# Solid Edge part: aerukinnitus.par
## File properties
Author: Argo
Template: Normal.par
Last saved by: Argo
Revision: 9
Application: Solid Edge
Material: ABS Plastic, medium impact
Face Style: Black
Fill Style: ANSI34(Plastic)
Virtual Style: Black (Shiny)
Coef. of Thermal Exp: 5.8e-05
Thermal Conductivity: 2.0
Specific Heat: 0.0
Modulus of Elasticity: 2275269810.0
Poission's Ratio: 0.4
Yield Stress: 43436969.1
Ultimate Stress: 0.0
Elongation: 0.0
Density: 1024,000 kg/m^3
Accuracy: 0,990
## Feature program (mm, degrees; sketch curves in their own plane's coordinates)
sketch for "unnamed Protrusion 1" plane through (0, 0, 0) normal (0, -1, 0) x-axis (1, 0, 0)
  line (5, 0) -> (5, 10)
  line (5, 10) -> (2.75, 10)
  line (2.75, 10) -> (2.75, 2)
  line (2.75, 2) -> (-2.75, 2)
  line (-2.75, 2) -> (-2.75, 10)
  line (-2.75, 10) -> (-5, 10)
  line (-5, 10) -> (-5, 0)
  line (-5, 0) -> (5, 0)
extrude "unnamed Protrusion 1" add finite 4 along -normal
fillet "Round_1" radius 1
sketch for "unnamed Cutout 1" plane through (0, 2, 2) normal (0, 0, 1) x-axis (1, 0, 0)
  circle centre (0, 0) radius 1.5
extrude "unnamed Cutout 1" cut to key point along -normal
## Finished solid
Body 1: solid body, 15 faces, 38 edges, 24 vertices.
  Faces by surface: plane 10, cylinder 5
  Edges by curve: line 28, circle 10
Bounding box of the edges (mm): 10.000 x 4.000 x 10.000, from (-5, 0, 0) to (5, 4, 10).
Cylindrical faces by radius (mm): R1 x4, R1.5 x1
Planar faces by outward normal: +x 2, +y 1, +z 3, -x 2, -y 1, -z 1
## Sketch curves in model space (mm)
circle centre (0, 2, 2) radius 1.5
line (5, 0, 0) -> (5, 0, 10)
line (5, 0, 10) -> (2.75, 0, 10)
line (2.75, 0, 10) -> (2.75, 0, 2)
line (2.75, 0, 2) -> (-2.75, 0, 2)
line (-2.75, 0, 2) -> (-2.75, 0, 10)
line (-2.75, 0, 10) -> (-5, 0, 10)
line (-5, 0, 10) -> (-5, 0, 0)
line (-5, 0, 0) -> (5, 0, 0)
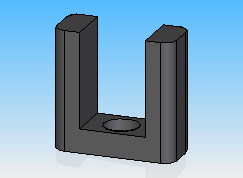
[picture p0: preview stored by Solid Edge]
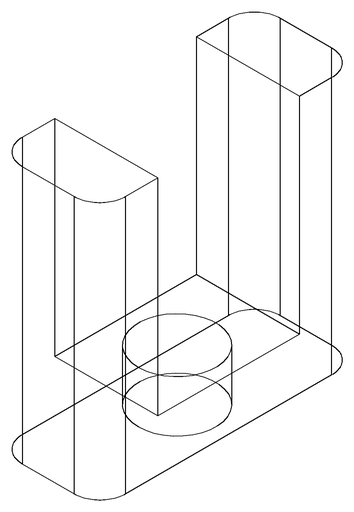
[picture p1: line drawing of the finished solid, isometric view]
